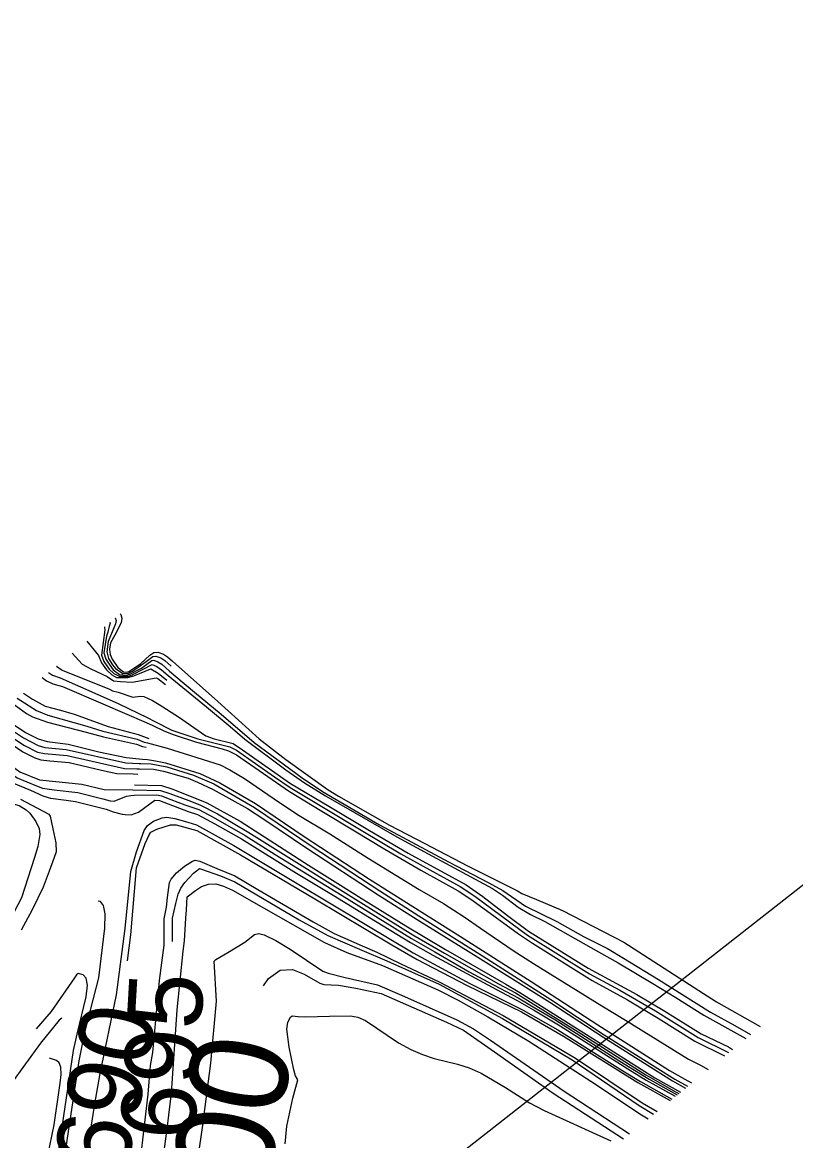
# Model space of a CAD drawing. Extents: x -291892836 to 2945206, y -477993085 to 1832792.
# Drawn here: x 1854108.7 to 1854368.1, y 545761 to 546136.2 of the extents above; entities that cross this region are included whole.
import ezdxf

# ---------------------------------------------------------------- set-up
doc = ezdxf.new("R2010")
doc.units = 0
for name, color, linetype in [('DT_X_Contour_Minor', 7, 'Continuous'), ('DT_X_Terrain_Ground_Line', 7, 'Continuous'), ('Level 63', 7, 'Continuous')]:
    doc.layers.add(name, color=color, linetype=linetype)

msp = doc.modelspace()

# ---------------------------------------------------------------- linework, layer by layer
at = {"layer": 'DT_X_Contour_Minor'}
for points in [[(1854141.51, 545937.76), (1854141.72, 545937.51), (1854142.11, 545936.21), (1854141.82, 545934.7), (1854139.69, 545930.55), (1854138.25, 545927.94), (1854137.9, 545925.85), (1854138.2, 545924.1), (1854138.85, 545922.47), (1854140.76, 545919.7), (1854142.58, 545918.21), (1854143.79, 545918.16), (1854144.47, 545918.34), (1854148.33, 545920.95), (1854151.45, 545923.89), (1854152.84, 545924.72), (1854154.14, 545924.9), (1854156.1, 545924.21), (1854157.44, 545923.28), (1854159.13, 545921.78)], [(1854136.21, 545933.41), (1854136.22, 545933.07), (1854136.41, 545932.34), (1854135.22, 545923.82), (1854136.07, 545921.71), (1854137.88, 545919.11), (1854139.43, 545917.74), (1854141.15, 545916.82), (1854144.42, 545916.85), (1854145.71, 545917.37), (1854152.21, 545920.73), (1854153.78, 545920.03), (1854155.43, 545918.88), (1854157.66, 545917.04)], [(1854138.09, 545934.95), (1854138.18, 545934.64), (1854137.82, 545933.44), (1854137.51, 545932.17), (1854137.39, 545931.56), (1854136.95, 545930.18), (1854136.05, 545924.59), (1854136.69, 545922.55), (1854137.77, 545920.8), (1854139.2, 545918.93), (1854141.3, 545917.34), (1854143.55, 545917.19), (1854144.72, 545917.43), (1854148.66, 545919.54), (1854150.43, 545920.83), (1854152.1, 545922.02), (1854152.86, 545922.12), (1854154.17, 545921.63), (1854155.48, 545920.81), (1854158.12, 545918.52)], [(1854139.82, 545936.38), (1854139.87, 545936.33), (1854140.14, 545935.43), (1854139.95, 545934.38), (1854137.47, 545928.41), (1854136.99, 545924.96), (1854137.62, 545922.77), (1854138.95, 545920.56), (1854139.93, 545919.36), (1854142.46, 545917.7), (1854144.28, 545917.76), (1854145.65, 545918.53), (1854150.28, 545921.77), (1854152.47, 545923.37), (1854153.5, 545923.51), (1854155.13, 545922.92), (1854156.46, 545922.05), (1854158.62, 545920.12)], [(1854130.36, 545928.6), (1854134.23, 545923.73), (1854135.22, 545921.33), (1854136.94, 545918.89), (1854138.67, 545917.3), (1854140.24, 545916.38), (1854144.09, 545916.3), (1854146.13, 545916.97), (1854151.84, 545919.25), (1854154.28, 545917.84), (1854157.18, 545915.47)], [(1854125.39, 545924.52), (1854128.74, 545920.83), (1854131.66, 545919.28), (1854137.16, 545916.66), (1854139.25, 545915.26), (1854141.68, 545914.98), (1854145.54, 545914.78), (1854153.6, 545916.29), (1854154.12, 545916), (1854156.72, 545913.99)], [(1854159.13, 545921.78), (1854174.32, 545908.25), (1854188.18, 545895.73), (1854197.1, 545888.8), (1854211.27, 545878.71), (1854214.79, 545876.54), (1854231.84, 545866.81), (1854243.77, 545860.61), (1854258.06, 545853.13), (1854274.85, 545844.79), (1854276.31, 545843.91), (1854281.19, 545841.83), (1854289.97, 545838.13), (1854310.52, 545827.53), (1854334.07, 545812.37), (1854341.6, 545807.56), (1854356.29, 545799.25)], [(1854117.5, 545918.04), (1854118.81, 545917.1), (1854121.36, 545916.21), (1854140.81, 545907.64), (1854150.75, 545902.77), (1854152.9, 545901.7)], [(1854120.1, 545920.17), (1854122.01, 545918.85), (1854137.91, 545912.41), (1854138.92, 545911.93), (1854140.83, 545911.48), (1854145.73, 545909.78), (1854148.24, 545910.1), (1854149.49, 545909.93), (1854152.36, 545908.64), (1854154.62, 545907.24)], [(1854158.12, 545918.52), (1854160.2, 545916.72), (1854166.41, 545911.46), (1854175.41, 545904.08), (1854186.49, 545894.56), (1854202.53, 545882.64), (1854209.43, 545878.07), (1854228.57, 545866.88), (1854251.7, 545854.49), (1854265.17, 545847.44), (1854269.93, 545844.84), (1854277.48, 545839.67), (1854288.06, 545834.47), (1854296.97, 545829.5), (1854305.05, 545825.4), (1854310.4, 545822.19), (1854322.12, 545815.04), (1854330, 545810.11), (1854339.62, 545804.06), (1854347.7, 545799.57), (1854353.03, 545796.58)], [(1854115.38, 545916.3), (1854116.8, 545915.28), (1854118.95, 545914.24), (1854122.15, 545913.28), (1854135.72, 545907.47), (1854150.29, 545901.24), (1854152.45, 545900.23)], [(1854157.66, 545917.04), (1854170.43, 545906.52), (1854178.37, 545899.9), (1854183.37, 545895.68), (1854197.07, 545885.42), (1854203.31, 545881.06), (1854210.37, 545876.69), (1854234.3, 545862.95), (1854244.86, 545857.16), (1854266.49, 545845.52), (1854269.76, 545843.28), (1854275.08, 545839.26), (1854279.17, 545836.88), (1854283.99, 545834.44), (1854301.99, 545824.33), (1854308.63, 545820.62), (1854320.25, 545813.69), (1854327.96, 545808.98), (1854337.31, 545803.05), (1854351.46, 545795.28)], [(1854109.13, 545911.15), (1854112.07, 545909.04), (1854116.32, 545906.79), (1854121.5, 545905.37), (1854126.04, 545904.02), (1854137.45, 545899.9), (1854147.58, 545897.27), (1854151.09, 545895.86)], [(1854105.18, 545907.91), (1854110.14, 545904.26), (1854112.07, 545903.11), (1854117.19, 545901.36), (1854130.13, 545898), (1854135.89, 545896.5), (1854146.96, 545894), (1854149.04, 545893.22), (1854150.2, 545892.97)], [(1854106.96, 545909.37), (1854113.47, 545905.23), (1854117.3, 545903.71), (1854130.32, 545899.99), (1854135.74, 545898.37), (1854147.27, 545895.64), (1854149.6, 545894.67), (1854150.64, 545894.4)], [(1854154.62, 545907.24), (1854161.12, 545903.2), (1854170.31, 545896.79), (1854173.07, 545895.81), (1854179.39, 545894.21), (1854182.6, 545892.08), (1854198.72, 545880.78), (1854211.5, 545873.16), (1854225.13, 545865.07), (1854238.2, 545857.37), (1854257.66, 545846.75), (1854263.22, 545842.85), (1854271.51, 545836.46), (1854278.57, 545831.27), (1854298.54, 545818.83), (1854314.83, 545809.98), (1854324.23, 545804.44), (1854336.49, 545796.74), (1854345.59, 545792.42), (1854346.96, 545791.59)], [(1854098.95, 545902.79), (1854109.12, 545896.14), (1854114.03, 545893.51), (1854116.29, 545892.89), (1854123.44, 545892.25), (1854143.37, 545887.71), (1854147.91, 545887.46), (1854148.48, 545887.45)], [(1854100.46, 545904.03), (1854109.72, 545897.95), (1854114.04, 545895.73), (1854117.07, 545894.88), (1854124.05, 545893.98), (1854134.36, 545891.44), (1854143.52, 545889.49), (1854148.96, 545889)], [(1854095.84, 545900.24), (1854108.87, 545891.42), (1854112.92, 545889.41), (1854114.9, 545888.75), (1854117.95, 545888.44), (1854124.38, 545887.83), (1854135.2, 545885.31), (1854140.36, 545884.15), (1854145.89, 545884), (1854147.4, 545883.97)], [(1854097.38, 545901.5), (1854109.46, 545893.5), (1854113.8, 545891.34), (1854116.14, 545890.81), (1854123.68, 545890.13), (1854142.95, 545885.85), (1854147.12, 545885.75), (1854147.95, 545885.73)], [(1854152.45, 545900.23), (1854156.14, 545898.51), (1854159.25, 545897.25), (1854167.14, 545894.68), (1854175.76, 545892.46), (1854177.9, 545891.8), (1854180.54, 545890.39), (1854189.59, 545884.12), (1854198.31, 545878.09), (1854209.2, 545871.56), (1854220.14, 545864.96), (1854230.33, 545858.78), (1854242.41, 545851.76), (1854254.88, 545844.81), (1854259.56, 545841.73), (1854275.14, 545830.3), (1854279.82, 545827.19), (1854299.93, 545814.74), (1854311.75, 545808.23), (1854322.06, 545802.02), (1854334.36, 545794.3), (1854344.25, 545789.37)], [(1854152.9, 545901.7), (1854158.83, 545898.72), (1854167.57, 545895.8), (1854178.27, 545893.14), (1854180.51, 545891.97), (1854193.29, 545882.98), (1854198.52, 545879.44), (1854210.35, 545872.36), (1854222.43, 545865.13), (1854235.63, 545857.23), (1854243.23, 545853), (1854255.56, 545846.23), (1854260.46, 545842.99), (1854278.18, 545829.87), (1854298.95, 545816.95), (1854309.15, 545811.44), (1854321.12, 545804.52), (1854335.42, 545795.52), (1854345.61, 545790.48)], [(1854089.77, 545895.25), (1854098.25, 545888.4), (1854099.97, 545887.38), (1854107, 545882.74), (1854113.46, 545880.03), (1854115.45, 545879.21), (1854119.33, 545878.7), (1854127.28, 545877.81), (1854135.74, 545875.7), (1854138.18, 545874.92), (1854139.51, 545874.85), (1854143.68, 545876.52), (1854145.15, 545876.72)], [(1854091.7, 545896.83), (1854100.38, 545890.05), (1854107.83, 545884.75), (1854114.48, 545882.03), (1854128.68, 545880.6), (1854136.14, 545878.81), (1854145.74, 545878.62)], [(1854087.69, 545893.54), (1854093.87, 545888.41), (1854096.92, 545885.87), (1854098.78, 545884.95), (1854100.97, 545883.63), (1854105.12, 545881.11), (1854111.46, 545878.6), (1854115.55, 545876.65), (1854118.17, 545875.9), (1854123.36, 545875.25), (1854126.49, 545874.76), (1854136.8, 545872.22), (1854139.21, 545871.31), (1854142.22, 545870.48), (1854143.2, 545870.43)], [(1854150.64, 545894.4), (1854157.28, 545892.67), (1854175.07, 545887.04), (1854178.32, 545885.42), (1854183.18, 545882.51), (1854193.13, 545875.67), (1854201.07, 545870.44), (1854211.88, 545863.86), (1854224.75, 545855.69), (1854241.84, 545845.26), (1854249.95, 545840.51), (1854256.88, 545836.01), (1854262.39, 545832.21), (1854273.41, 545824.74), (1854280.15, 545820.43), (1854303.08, 545806.17), (1854311.62, 545801.06), (1854332.2, 545788.29), (1854336.23, 545786.25), (1854338.76, 545784.85)], [(1854081.44, 545888.4), (1854085.87, 545884.37), (1854091.58, 545879.43), (1854095.69, 545876.58), (1854098.1, 545875.78), (1854099.72, 545875.58), (1854107.64, 545873.37), (1854109.97, 545871.93), (1854111.24, 545870.81), (1854113.27, 545867.99), (1854114.38, 545865.67), (1854114.57, 545863.69), (1854113.88, 545859.64), (1854112.79, 545855.98), (1854108.38, 545842.38), (1854104.63, 545835.12), (1854101.63, 545830.43), (1854096.5, 545824.1)], [(1854148.96, 545889), (1854150.72, 545888.84), (1854153.39, 545888.42), (1854156.72, 545887.73), (1854168.27, 545884.09), (1854174.93, 545881.05), (1854186.92, 545874.05), (1854203.25, 545863.06), (1854225.14, 545848.72), (1854239.7, 545839.48), (1854255.65, 545829.49), (1854279.43, 545814.3), (1854301.76, 545799.76), (1854325.82, 545784.52), (1854330.94, 545781.62), (1854333.25, 545780.33)], [(1854147.95, 545885.73), (1854152.75, 545885.61), (1854156.07, 545884.96), (1854164.31, 545882.56), (1854167.48, 545881.28), (1854172.69, 545878.78), (1854184.24, 545872.4), (1854189.7, 545868.79), (1854204.48, 545858.88), (1854228.07, 545843.48), (1854241.22, 545835.15), (1854262.36, 545822.01), (1854285.68, 545807.38), (1854303.75, 545795.51), (1854326.78, 545781.06), (1854331.16, 545778.61)], [(1854148.48, 545887.45), (1854151.94, 545887.39), (1854157.14, 545886.35), (1854166.09, 545883.61), (1854172.91, 545880.63), (1854186.59, 545872.79), (1854205.55, 545859.92), (1854228.63, 545844.73), (1854241.75, 545836.4), (1854263.06, 545823), (1854285.97, 545808.3), (1854303.95, 545796.47), (1854327.56, 545781.62), (1854331.88, 545779.2)], [(1854146.27, 545880.33), (1854155.33, 545880.07), (1854159.19, 545878.9), (1854170.62, 545874.33), (1854181.78, 545868.14), (1854188.35, 545863.89), (1854204.7, 545853.4), (1854214.58, 545847.27), (1854223.29, 545841.81), (1854237.32, 545832.98), (1854250.71, 545825.06), (1854270.94, 545813.42), (1854275.64, 545810.66), (1854298, 545796.54), (1854320.9, 545782.07), (1854329.48, 545777.22)], [(1854145.15, 545876.72), (1854146.18, 545876.86), (1854153.85, 545876.98), (1854155.33, 545876.68), (1854158.54, 545875.41), (1854163.25, 545873.6), (1854167.88, 545872.03), (1854172.75, 545869.45), (1854183.45, 545863.3), (1854193.51, 545856.98), (1854216.01, 545843.16), (1854239.31, 545828.74), (1854247.04, 545824.27), (1854258.57, 545817.63), (1854264.88, 545814.22), (1854275.05, 545808.91), (1854280.68, 545805.52), (1854287.32, 545801.59), (1854309.18, 545787.65), (1854318.99, 545781.55), (1854328.35, 545776.29)], [(1854145.74, 545878.62), (1854155.09, 545878.44), (1854158.14, 545877.46), (1854164.59, 545875.06), (1854168.26, 545873.67), (1854174.13, 545870.56), (1854184.7, 545864.4), (1854194.52, 545858.15), (1854218.16, 545843.48), (1854239.69, 545830.02), (1854250.34, 545823.86), (1854268.48, 545813.56), (1854274.14, 545810.54), (1854295.17, 545797.44), (1854317.89, 545783.04), (1854328.09, 545777.22), (1854328.91, 545776.76)], [(1854108.1, 545875.49), (1854117.61, 545870.48), (1854117.98, 545869.86), (1854118.9, 545865.61), (1854119.95, 545860.83), (1854120, 545857.82), (1854119.4, 545855.99), (1854117.68, 545851.41), (1854115.72, 545846.05), (1854112.04, 545838.41), (1854108.32, 545831.55)], [(1854143.2, 545870.43), (1854145.21, 545870.32), (1854147.67, 545871.22), (1854153.12, 545875.19), (1854154.75, 545875.14), (1854164.38, 545871.43), (1854167.51, 545870.39), (1854173.3, 545867.28), (1854182.2, 545862.2), (1854200.7, 545850.71), (1854213.02, 545843.31), (1854225.21, 545835.8), (1854238.93, 545827.45), (1854246.43, 545823.19), (1854267.74, 545811.68), (1854274.75, 545808.03), (1854280.23, 545804.8), (1854289.1, 545799.52), (1854311.86, 545785.06), (1854318.03, 545781.3), (1854327.78, 545775.83)], [(1854129.47, 545750.36), (1854132.99, 545773.35), (1854134.79, 545783.49), (1854140.33, 545809.84), (1854143.18, 545832.14), (1854145.11, 545851.31), (1854146.99, 545857.86), (1854149.58, 545865.05), (1854150.69, 545866.66), (1854152.65, 545868.16), (1854155.62, 545869.29), (1854157.16, 545869.5), (1854159.86, 545869.01), (1854164.21, 545867.79), (1854167.17, 545866.91), (1854179.7, 545860.01), (1854200.3, 545847.56), (1854224.25, 545833.25), (1854239.83, 545823.93), (1854258.85, 545813.72), (1854276.78, 545804.76), (1854288.32, 545798.18), (1854310.75, 545784.02), (1854316.12, 545780.78), (1854326.65, 545774.9)], [(1854143.97, 545821.24), (1854145.05, 545829.98), (1854147.04, 545852.5), (1854149.86, 545860.69), (1854151.19, 545863.61), (1854151.86, 545864.44), (1854153.8, 545865.44), (1854158.42, 545866.87), (1854160.28, 545866.88), (1854167.24, 545865.02), (1854181.84, 545856.91), (1854206.81, 545842.09), (1854232.65, 545826.66), (1854241.22, 545821.72), (1854257.93, 545812.98), (1854276.14, 545804.13), (1854290.25, 545796.06), (1854315.16, 545780.52), (1854326.08, 545774.43)], [(1854148.52, 545756.38), (1854150.94, 545776.56), (1854151.68, 545786.14), (1854152.53, 545790.54), (1854154.75, 545814.7), (1854156.24, 545826.59), (1854156.27, 545835.43), (1854157.03, 545839.3), (1854157.37, 545842.57), (1854158.12, 545847.59), (1854158.61, 545848.68), (1854160.4, 545850.84), (1854163.07, 545853.04), (1854165.76, 545854.72), (1854166.72, 545855.03), (1854168.27, 545854.72), (1854173.91, 545852.3), (1854179.97, 545849.76), (1854187.72, 545845.22), (1854206.26, 545834.37), (1854213.29, 545830.49), (1854222.69, 545826.34), (1854227.61, 545824.15), (1854235.73, 545820.25), (1854248.54, 545814.28), (1854269.97, 545802.91), (1854294.31, 545788.6), (1854316.6, 545773.68), (1854321.64, 545770.78)], [(1854159.09, 545827.79), (1854159.08, 545828.79), (1854159.1, 545835.65), (1854160.19, 545840.49), (1854160.93, 545843.67), (1854161.82, 545845.64), (1854163.18, 545847.58), (1854166.1, 545850.69), (1854168.16, 545852.27), (1854168.8, 545852.08), (1854175.18, 545849.76), (1854179.94, 545847.8), (1854201.58, 545835.02), (1854211.21, 545829.78), (1854222.58, 545824.84), (1854231.04, 545821.28), (1854248.56, 545813.41), (1854269.8, 545801.91), (1854293.12, 545788.1), (1854315.67, 545772.78), (1854320.5, 545769.85)], [(1854155.11, 545749.08), (1854157.41, 545765.83), (1854158.77, 545776.88), (1854160.67, 545804.81), (1854162.66, 545824.54), (1854163.13, 545828.05), (1854163.53, 545835.56), (1854163.77, 545838.43), (1854163.99, 545842.77), (1854166.77, 545844.94), (1854168.82, 545846.2), (1854171.14, 545847.04), (1854173.57, 545847.09), (1854176.22, 545846.35), (1854179.25, 545844.97), (1854189.62, 545839.1), (1854210.11, 545827.42), (1854217.53, 545824.11), (1854229.51, 545819.73), (1854248.06, 545811.55)], [(1854120.95, 545741.82), (1854123.84, 545761.74), (1854127.71, 545787.76), (1854129.64, 545797.28), (1854131.6, 545804.77), (1854134.38, 545815.6), (1854136.42, 545832.24), (1854136.53, 545837.03), (1854135.92, 545839.88), (1854134.9, 545841.15), (1854134.17, 545841.34)], [(1854165.36, 545739.14), (1854169.12, 545765.4), (1854171.95, 545786.95), (1854173.83, 545807.74), (1854173.06, 545821.23), (1854173.63, 545821.78), (1854177.59, 545824.12), (1854183.33, 545827.52), (1854186.61, 545830.07), (1854188.03, 545830.46), (1854189.88, 545830.05), (1854193.77, 545828.16), (1854198.59, 545825.18), (1854209.54, 545817.86), (1854211.25, 545817.11), (1854217.01, 545815.7), (1854227.8, 545813.19), (1854235.87, 545809.72), (1854254.44, 545801.47), (1854260.07, 545798.42), (1854265.77, 545794.62), (1854290.46, 545777.55), (1854312.4, 545763.19)], [(1854118.63, 545742.35), (1854121.64, 545762.43), (1854125.85, 545791.25), (1854127.05, 545796.63), (1854130.08, 545809.21), (1854130.52, 545813.09), (1854130.07, 545815.44), (1854129.09, 545816.55), (1854127.45, 545817.06), (1854126.85, 545816.57), (1854126.18, 545815.58)], [(1854189.65, 545812.92), (1854191.34, 545815.35), (1854195.22, 545818.2), (1854199.34, 545818.35), (1854203.23, 545816.78), (1854208.47, 545813.79), (1854209.85, 545813.4), (1854214.82, 545813.07), (1854220.63, 545812.16), (1854229.04, 545810.28), (1854251.06, 545800.7), (1854256.74, 545798.04), (1854267.1, 545790.71), (1854286.82, 545776.85), (1854310.36, 545761.51)], [(1854126.18, 545815.58), (1854118.42, 545804.25), (1854113.29, 545798.42)], [(1854248.06, 545811.55), (1854254.88, 545808.05), (1854264.88, 545802.55), (1854278.67, 545794.35), (1854301.36, 545779.64), (1854315.9, 545769.97), (1854318.63, 545768.31)], [(1854121.99, 545802.08), (1854121.07, 545801.34), (1854114.83, 545793.65), (1854104.72, 545779.84), (1854100.92, 545775.51), (1854097.83, 545772.65), (1854087.4, 545764.43), (1854079.9, 545759.44)], [(1854196.83, 545759.91), (1854197.42, 545765.86), (1854199.4, 545775.19), (1854201.11, 545781.32), (1854200.39, 545782.71), (1854199.77, 545784.77), (1854198.27, 545792.32), (1854197.46, 545798.37), (1854197.74, 545800.74), (1854198.66, 545802.36), (1854199.26, 545802.8), (1854201.29, 545802.63), (1854203.67, 545802.46), (1854211.79, 545802.7), (1854218.81, 545802.89), (1854221.23, 545802.44), (1854223.79, 545801.22), (1854234.95, 545793.74), (1854238.99, 545791.54), (1854242.96, 545789.84), (1854246.88, 545788.56), (1854254.66, 545786.65), (1854258.62, 545785.38), (1854262.68, 545783.55), (1854270.77, 545778.77), (1854278.88, 545773.66), (1854283.77, 545771.07), (1854306.17, 545760.94)], [(1854117.24, 545755.98), (1854119.35, 545766.28), (1854121.43, 545780.29), (1854121.7, 545783.18), (1854121.63, 545785.6), (1854121.05, 545787.1), (1854120.18, 545787.85), (1854117.81, 545788.64)]]:
    msp.add_lwpolyline(points, dxfattribs=at)
at = {"layer": 'Level 63'}
msp.add_line((1853782.96, 545386.45), (1854903.14, 546264.01), dxfattribs=at)

# ---------------------------------------------------------------- texts
at = {"layer": 'DT_X_Terrain_Ground_Line'}
for s, height, rotation, p in [('695', 25, 86.6942, (1854166.44, 545760.81)), ('690', 25, 78.69, (1854143.25, 545748.77)), ('700', 33, 79.6068, (1854186.48, 545720.1))]:
    msp.add_text(s, height=height, rotation=rotation, dxfattribs=at).set_placement(p)

doc.saveas('drawing.dxf')
